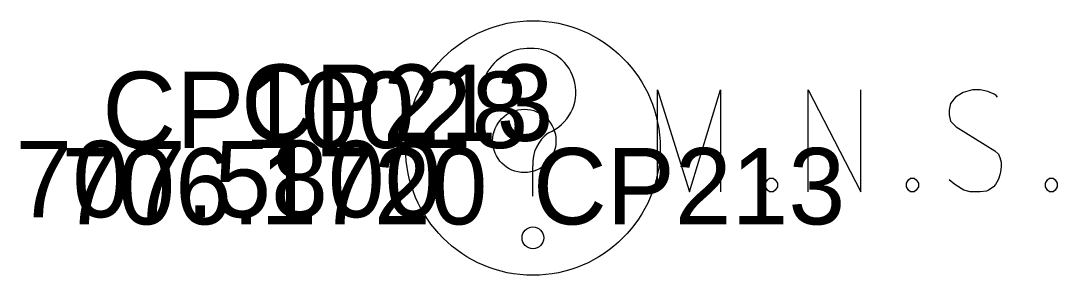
# Model space of a CAD drawing. Extents: x 182090 to 1832865, y 706265 to 714392.
# Drawn here: x 1822256.888 to 1822260.959, y 711874.371 to 711875.371 of the extents above; entities that cross this region are included whole.
import ezdxf

# ---------------------------------------------------------------- set-up
doc = ezdxf.new("R2010")
doc.units = 0
for name, color, linetype in [('RD_X_Misc_Items', 7, 'Continuous'), ('SV_P_Control_Cells_Set', 7, 'Continuous'), ('SV_X_Text_Comment', 7, 'Continuous'), ('SV_X_Text_Elevation', 7, 'Continuous'), ('SV_X_Text_Name', 7, 'Continuous')]:
    doc.layers.add(name, color=color, linetype=linetype)

msp = doc.modelspace()

# ---------------------------------------------------------------- linework, layer by layer
at = {"layer": 'RD_X_Misc_Items'}
msp.add_line((1822258.9, 711874.6822), (1822258.9, 711874.801), dxfattribs=at)
for centre, radius in [((1822258.9, 711874.871), 0.5), ((1822258.9, 711874.5181), 0.0426)]:
    msp.add_circle(centre, radius, dxfattribs=at)
for centre, radius, start, end in [((1822258.8841, 711875.0738), 0.1885, 88.324, 152.5385), ((1822258.897, 711875.0905), 0.1719, 291.9329, 92.4584), ((1822259.0464, 711874.8115), 0.1468, 125.4618, 184.0829)]:
    msp.add_arc(centre, radius, start, end, dxfattribs=at)
at = {"layer": 'SV_P_Control_Cells_Set'}
for points in [[(1822259.3886, 711874.6989), (1822259.3886, 711875.0989), (1822259.5154, 711874.6989), (1822259.6366, 711875.0989), (1822259.6366, 711874.6989)], [(1822259.9811, 711874.6989), (1822259.9811, 711875.0989), (1822260.1878, 711874.6989), (1822260.1878, 711875.0989)], [(1822260.7252, 711875.0705), (1822260.7196, 711875.0768), (1822260.7114, 711875.0831), (1822260.6866, 711875.0926), (1822260.6562, 711875.0989), (1822260.6342, 711875.0989), (1822260.6259, 711875.0989), (1822260.5901, 711875.0894), (1822260.5598, 711875.0705), (1822260.5405, 711875.0453), (1822260.535, 711875.0201), (1822260.535, 711875.0012), (1822260.5405, 711874.976), (1822260.5625, 711874.954), (1822260.7141, 711874.8595), (1822260.7279, 711874.8469), (1822260.7334, 711874.8343), (1822260.7389, 711874.8154), (1822260.7389, 711874.7965), (1822260.7362, 711874.7776), (1822260.7334, 711874.765), (1822260.7279, 711874.7492), (1822260.7224, 711874.7366), (1822260.7169, 711874.7272), (1822260.7086, 711874.7178), (1822260.7003, 711874.7115), (1822260.6893, 711874.7052), (1822260.6811, 711874.702), (1822260.6562, 711874.6989), (1822260.6177, 711874.6989), (1822260.5929, 711874.7052), (1822260.557, 711874.7272), (1822260.535, 711874.7461)], [(1822259.8296, 711874.7524), (1822259.8433, 711874.7524), (1822259.8516, 711874.7461), (1822259.8599, 711874.7335), (1822259.8599, 711874.7178), (1822259.8516, 711874.7052), (1822259.8433, 711874.6989), (1822259.8296, 711874.6989), (1822259.8213, 711874.7052), (1822259.813, 711874.7178), (1822259.813, 711874.7335), (1822259.8213, 711874.7461), (1822259.8296, 711874.7524)], [(1822260.3834, 711874.7524), (1822260.3972, 711874.7524), (1822260.4055, 711874.7461), (1822260.4137, 711874.7335), (1822260.4137, 711874.7178), (1822260.4055, 711874.7052), (1822260.3972, 711874.6989), (1822260.3834, 711874.6989), (1822260.3752, 711874.7052), (1822260.3669, 711874.7178), (1822260.3669, 711874.7335), (1822260.3752, 711874.7461), (1822260.3834, 711874.7524)], [(1822260.9291, 711874.7524), (1822260.9428, 711874.7524), (1822260.9511, 711874.7461), (1822260.9594, 711874.7335), (1822260.9594, 711874.7178), (1822260.9511, 711874.7052), (1822260.9428, 711874.6989), (1822260.9291, 711874.6989), (1822260.9208, 711874.7052), (1822260.9125, 711874.7178), (1822260.9125, 711874.7335), (1822260.9208, 711874.7461), (1822260.9291, 711874.7524)]]:
    msp.add_lwpolyline(points, dxfattribs=at)
msp.add_circle((1822258.8661, 711874.8989), 0.1244, dxfattribs=at)

# ---------------------------------------------------------------- texts
at = {"layer": 'SV_X_Text_Comment'}
msp.add_text('CP213', height=0.3, dxfattribs=at).set_placement((1822258.9, 711874.571))
at = {"layer": 'SV_X_Text_Elevation'}
for s, p in [('707.5800', (1822256.8677, 711874.599)), ('706.1720', (1822257.0483, 711874.571))]:
    msp.add_text(s, height=0.3, dxfattribs=at).set_placement(p)
at = {"layer": 'SV_X_Text_Name'}
for s, p in [('CP213', (1822257.7536, 711874.899)), ('CP10028', (1822257.2089, 711874.871))]:
    msp.add_text(s, height=0.3, dxfattribs=at).set_placement(p)

doc.saveas('drawing.dxf')
